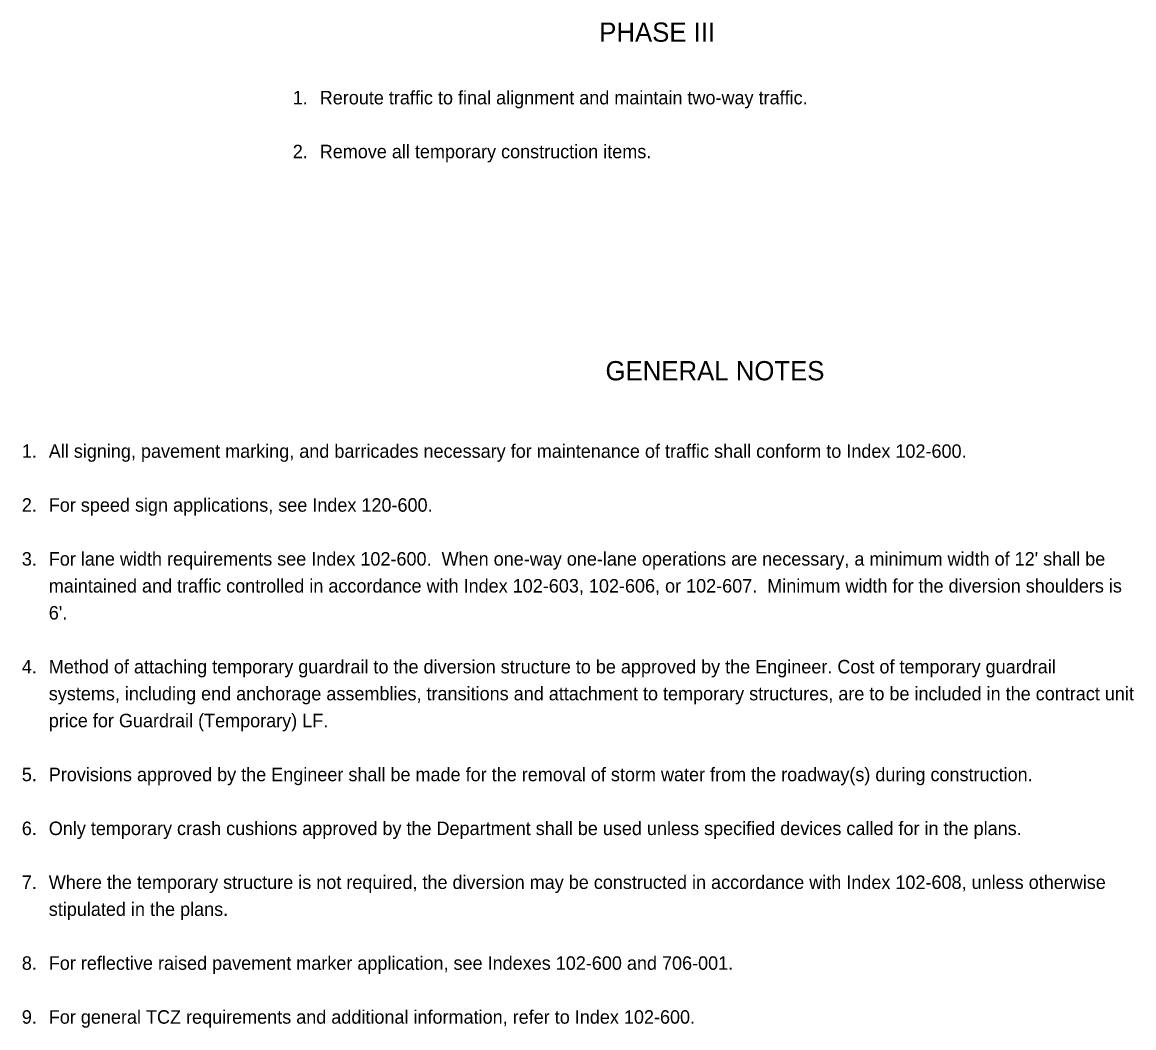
# Model space of a CAD drawing. Extents: x 10244 to 10532, y 10177 to 10439.
import ezdxf

# ---------------------------------------------------------------- set-up
doc = ezdxf.new("R2010")
doc.units = 0
doc.layers.add('Dimension', color=7, linetype='Continuous')

msp = doc.modelspace()

# ---------------------------------------------------------------- texts
at = {"layer": 'Dimension'}
for s, height, p in [('PHASE III', 5, (10393.55, 10433.49)), ('1.', 3.5, (10313.98, 10417.23)), ('Reroute traffic to final alignment and maintain two-way traffic.', 3.5, (10320.98, 10417.23)), ('2.', 3.5, (10313.98, 10403.23)), ('Remove all temporary construction items.', 3.5, (10320.98, 10403.23)), ('GENERAL NOTES', 5, (10395.18, 10345.54)), ('1.', 3.5, (10243.63, 10325.41)), ('All signing, pavement marking, and barricades necessary for maintenance of traffic shall conform to Index 102-600.', 3.5, (10250.63, 10325.41)), ('2.', 3.5, (10243.63, 10311.41)), ('For speed sign applications, see Index 120-600.', 3.5, (10250.63, 10311.41)), ('3.', 3.5, (10243.63, 10297.41)), ("For lane width requirements see Index 102-600.  When one-way one-lane operations are necessary, a minimum width of 12' shall be ", 3.5, (10250.63, 10297.41)), ('maintained and traffic controlled in accordance with Index 102-603, 102-606, or 102-607.  Minimum width for the diversion shoulders is ', 3.5, (10250.63, 10290.41)), ("6'.", 3.5, (10250.63, 10283.41)), ('4.', 3.5, (10243.63, 10269.41)), ('Method of attaching temporary guardrail to the diversion structure to be approved by the Engineer. Cost of temporary guardrail ', 3.5, (10250.63, 10269.41)), ('systems, including end anchorage assemblies, transitions and attachment to temporary structures, are to be included in the contract unit ', 3.5, (10250.63, 10262.41)), ('price for Guardrail (Temporary) LF.', 3.5, (10250.63, 10255.41)), ('5.', 3.5, (10243.63, 10241.41)), ('Provisions approved by the Engineer shall be made for the removal of storm water from the roadway(s) during construction.', 3.5, (10250.63, 10241.41)), ('6.', 3.5, (10243.63, 10227.41)), ('Only temporary crash cushions approved by the Department shall be used unless specified devices called for in the plans.', 3.5, (10250.63, 10227.41)), ('7.', 3.5, (10243.63, 10213.41)), ('Where the temporary structure is not required, the diversion may be constructed in accordance with Index 102-608, unless otherwise ', 3.5, (10250.63, 10213.41)), ('stipulated in the plans.', 3.5, (10250.63, 10206.41)), ('8.', 3.5, (10243.63, 10192.41)), ('For reflective raised pavement marker application, see Indexes 102-600 and 706-001.', 3.5, (10250.63, 10192.41)), ('For general TCZ requirements and additional information, refer to Index 102-600.', 3.5, (10250.63, 10178.41)), ('9.', 3.5, (10243.63, 10178.41))]:
    msp.add_text(s, height=height, dxfattribs=at).set_placement(p)

doc.saveas('drawing.dxf')
